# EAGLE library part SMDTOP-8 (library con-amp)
AMP connector
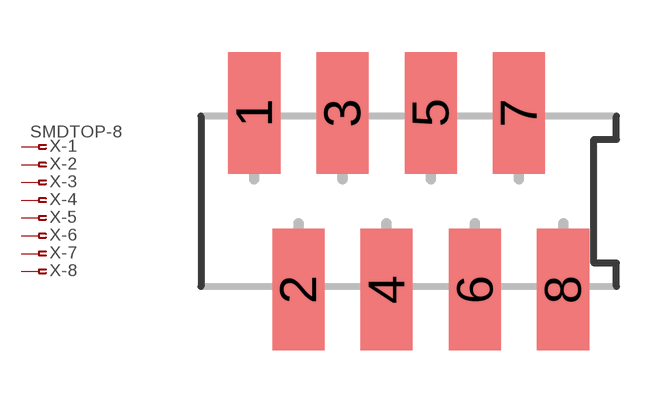
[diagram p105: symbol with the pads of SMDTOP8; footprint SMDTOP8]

Designator prefix X; gates -1=PIN-FV -2=PIN-F -3=PIN-F -4=PIN-F -5=PIN-F -6=PIN-F -7=PIN-F -8=PIN-F

## SMDTOP-8 (OC_FARNELL: unknown; OC_NEWARK: unknown)  [SMDTOP8]
1  -1:1  pas
2  -2:1  pas
3  -3:1  pas
4  -4:1  pas
5  -5:1  pas
6  -6:1  pas
7  -7:1  pas
8  -8:1  pas

## Footprint SMDTOP8 (pad centres in mm)
AMP connector
smd 1.5 x 3.5: 1 -4.445,2.54; 2 -3.175,-2.54; 3 -1.905,2.54; 4 -0.635,-2.54; 5 0.635,2.54; 6 1.905,-2.54; 7 3.175,2.54; 8 4.445,-2.54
